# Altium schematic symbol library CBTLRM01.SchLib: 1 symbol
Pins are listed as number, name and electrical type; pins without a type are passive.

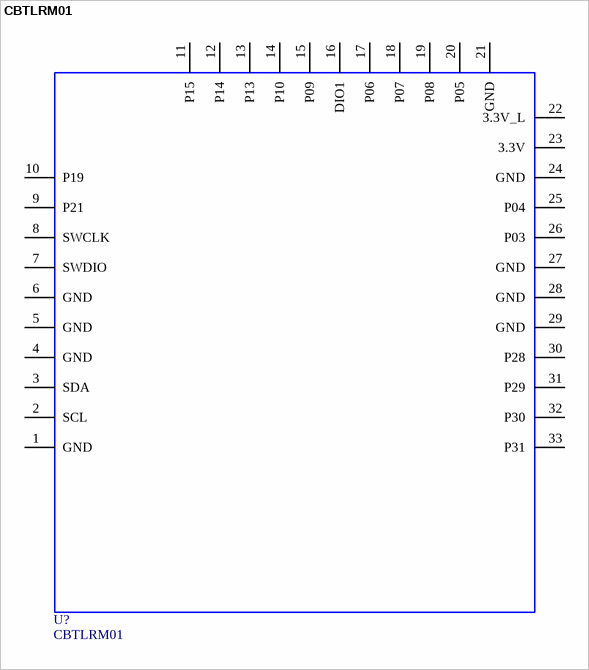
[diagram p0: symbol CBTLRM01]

## CBTLRM01
designator U?
module CBTLRM01
footprint CBTLRM01
pins: 1 GND, 2 SCL, 3 SDA, 4 GND, 5 GND, 6 GND, 7 SWDIO, 8 SWCLK, 9 P21, 10 P19, 11 P15, 12 P14, 13 P13, 14 P10, 15 P09, 16 DIO1, 17 P06, 18 P07, 19 P08, 20 P05, 21 GND, 22 3.3V_L, 23 3.3V, 24 GND, 25 P04, 26 P03, 27 GND, 28 GND, 29 GND, 30 P28, 31 P29, 32 P30, 33 P31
